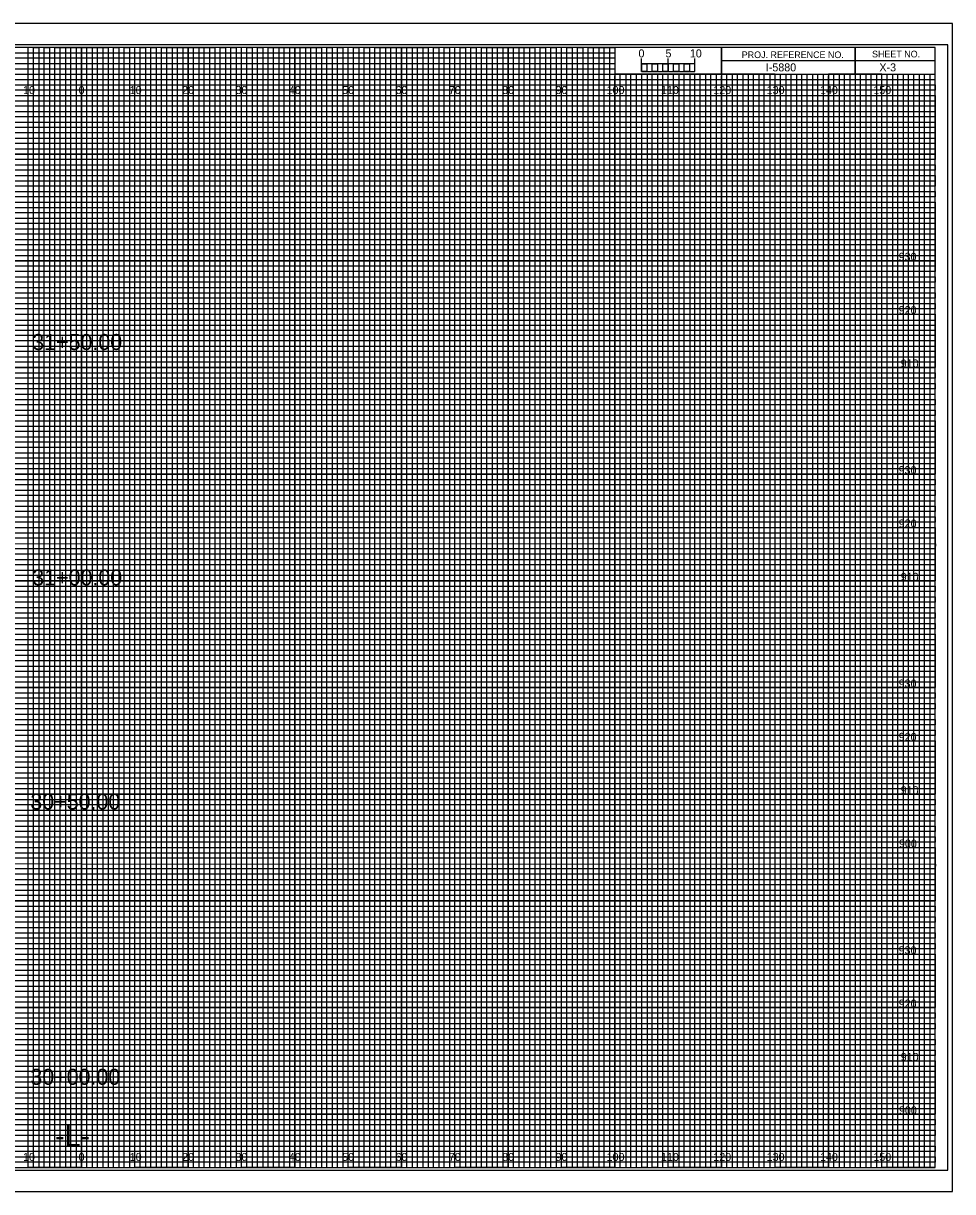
# Model space of a CAD drawing. Extents: x -13 to 323, y -4 to 3074.
# Drawn here: x 149.1 to 323.3, y 215.5 to 434.5 of the extents above; entities that cross this region are included whole.
import ezdxf

# ---------------------------------------------------------------- set-up
doc = ezdxf.new("R2010")
doc.units = 0
for name, color, linetype in [('Prop XS Alignment Label', 7, 'Continuous'), ('Prop XS Bar Scale Labels', 7, 'Continuous'), ('Prop XS Elevation Labels', 7, 'Continuous'), ('Prop XS Offset Labels', 7, 'Continuous'), ('Prop XS Project Number', 7, 'Continuous'), ('Prop XS Sheet Number', 7, 'Continuous'), ('Prop XS Station Labels', 7, 'Continuous'), ('Sheet Cross Section CELL', 7, 'Continuous'), ('Sheet Cross Section Grid Major CELL', 7, 'Continuous'), ('Sheet Cross Section Grid Middle CELL', 7, 'Continuous'), ('Sheet Cross Section Grid Minor 1 CELL', 7, 'Continuous'), ('Sheet Cross Section Grid Minor 2 CELL', 7, 'Continuous'), ('Sheet Cross Section Scale CELL', 7, 'Continuous'), ('Sheet Cutting Line CELL', 7, 'Continuous'), ('Sheet DOT Grid CELL', 7, 'Continuous'), ('Sheet Plot Border Inside CELL', 7, 'Continuous'), ('Sheet Plot Border Outside CELL', 7, 'Continuous')]:
    doc.layers.add(name, color=color, linetype=linetype)

msp = doc.modelspace()

# ---------------------------------------------------------------- linework, layer by layer
at = {"layer": 'Sheet Cross Section CELL'}
for p, q in [((305, 430), (305, 425)), ((305, 425), (305, 430)), ((280, 427.5), (280, 425)), ((320, 427.49), (280, 427.49)), ((280, 425), (320, 425))]:
    msp.add_line(p, q, dxfattribs=at)
for points in [[(320, 430), (0, 430), (0, 220), (320, 220)], [(280, 430), (260, 430), (260, 425.03), (280, 425.03)], [(320, 430), (280, 430), (280, 425), (320, 425)]]:
    msp.add_lwpolyline(points, close=True, dxfattribs=at)
at = {"layer": 'Sheet Cross Section Grid Major CELL'}
for p, q in [((150, 430), (140, 430)), ((150, 220), (150, 430)), ((170, 430), (160, 430)), ((160, 430), (160, 220)), ((170, 220), (170, 430)), ((190, 430), (180, 430)), ((180, 430), (180, 220)), ((190, 220), (190, 430)), ((210, 430), (200, 430)), ((200, 430), (200, 220)), ((210, 220), (210, 430)), ((230, 430), (220, 430)), ((220, 430), (220, 220)), ((230, 220), (230, 430)), ((250, 430), (240, 430)), ((240, 430), (240, 220)), ((250, 220), (250, 430)), ((260, 430), (260, 220)), ((270, 220), (270, 425)), ((290, 425), (280, 425)), ((280, 425), (280, 220)), ((290, 220), (290, 425)), ((310, 425), (300, 425)), ((300, 425), (300, 220)), ((310, 220), (310, 425)), ((160, 220), (150, 220)), ((180, 220), (170, 220)), ((200, 220), (190, 220)), ((220, 220), (210, 220)), ((240, 220), (230, 220)), ((260, 220), (250, 220)), ((280, 220), (270, 220)), ((300, 220), (290, 220)), ((320, 220), (310, 220)), ((320, 220), (320, 220))]:
    msp.add_line(p, q, dxfattribs=at)
for points in [[(0, 420), (320, 420), (320, 410), (0, 410)], [(0, 400), (320, 400), (320, 390), (0, 390)], [(0, 380), (320, 380), (320, 370), (0, 370)], [(0, 360), (320, 360), (320, 350), (0, 350)], [(0, 340), (320, 340), (320, 330), (0, 330)], [(0, 320), (320, 320), (320, 310), (0, 310)], [(0, 300), (320, 300), (320, 290), (0, 290)], [(0, 280), (320, 280), (320, 270), (0, 270)], [(0, 260), (320, 260), (320, 250), (0, 250)], [(0, 240), (320, 240), (320, 230), (0, 230)]]:
    msp.add_lwpolyline(points, dxfattribs=at)
at = {"layer": 'Sheet Cross Section Grid Middle CELL'}
for points in [[(145, 220), (155, 220), (155, 430), (165, 430), (165, 220), (175, 220), (175, 430), (185, 430), (185, 220), (195, 220), (195, 430), (205, 430), (205, 220), (215, 220), (215, 430), (225, 430), (225, 220), (235, 220), (235, 430), (245, 430), (245, 220), (255, 220), (255, 430), (259.93, 430), (260, 430), (260, 425), (264.99, 425), (264.99, 220), (275, 220), (275, 425), (285, 425), (285, 220), (295, 220), (295, 425), (305, 425), (305, 220), (315, 220), (315, 425)], [(0, 425), (275, 425)], [(0, 405), (320, 405), (320, 415), (0, 415)], [(0, 385), (320, 385), (320, 395), (0, 395)], [(0, 365), (320, 365), (320, 375), (0, 375)], [(0, 345), (320, 345), (320, 355), (0, 355)], [(0, 325), (320, 325), (320, 335), (0, 335)], [(0, 305), (320, 305), (320, 315), (0, 315)], [(0, 285), (320, 285), (320, 295), (0, 295)], [(0, 265), (320, 265), (320, 275), (0, 275)], [(0, 245), (320, 245), (320, 255), (0, 255)], [(0, 225), (320, 225), (320, 235), (0, 235)]]:
    msp.add_lwpolyline(points, dxfattribs=at)
at = {"layer": 'Sheet Cross Section Grid Minor 1 CELL'}
for p, q in [((0, 429), (260, 429)), ((260, 427.98), (0, 427.98)), ((260, 429), (260, 427.98)), ((0, 427), (260, 427)), ((260, 425.89), (0, 425.89)), ((260, 427), (260, 425.89)), ((0, 424), (320, 424))]:
    msp.add_line(p, q, dxfattribs=at)
for points in [[(0, 423), (270, 423), (320, 423), (320, 422), (0, 422)], [(0, 421), (320, 421), (320, 419), (0, 419)], [(0, 418), (320, 418), (320, 417), (0, 416.98)], [(0, 416), (320, 416), (320, 414), (0, 414)], [(0, 413), (320, 413), (320, 412), (0, 412)], [(0, 411), (320, 411), (320, 409), (0, 409)], [(0, 408), (320, 408), (320, 407), (0, 407)], [(0, 406), (320, 406), (320, 404), (0, 404)], [(0, 403), (320, 403), (320, 402), (0, 402)], [(0, 401), (320, 401), (320, 399), (0, 399)], [(0, 398), (320, 398), (320, 397), (0, 397)], [(0, 396), (320, 396), (320, 393.95), (320, 393), (320, 392), (0, 392)], [(0, 394), (320, 394), (320, 393), (0, 393)], [(0, 391), (320, 391), (320, 389), (0, 389.03)], [(0, 389.03), (320, 389), (320, 388), (0, 388)], [(0, 387), (320, 387), (320, 386), (0, 386)], [(0, 384), (320, 384), (320, 383), (0, 383)], [(0, 382), (320, 382), (320, 381), (0, 381)], [(-0.07, 378.89), (320, 378.89), (320, 377.88), (-0.07, 377.88)], [(0, 377), (320, 377), (320, 376), (0, 376)], [(0, 374), (320, 374), (320, 373), (0, 373)], [(0, 372), (320, 372), (320, 371), (0, 371)], [(0, 369), (320, 369), (320, 368), (0, 368)], [(0, 367), (320, 367), (320, 366), (0, 366)], [(0, 364), (320, 364), (320, 363), (0, 363)], [(0, 362), (320, 362), (320, 361), (0, 361)], [(0, 359), (320, 359), (319.99, 357.98), (0, 358)], [(0, 357), (320, 357), (320, 356), (0, 356)], [(0, 354), (320, 354), (320, 353), (0, 353)], [(0, 352), (320, 352), (320, 351), (0, 351)], [(0, 349), (320, 349), (320, 348), (0, 348)], [(0, 347), (320, 347), (320, 346), (0, 346)], [(0, 344), (320, 344), (320, 343), (0, 343)], [(0, 342), (320, 342), (320, 341), (0, 341)], [(0, 339), (320, 339), (320, 338), (0, 338)], [(0, 336.99), (320.07, 336.91), (320, 336), (0, 336)], [(0, 334), (320, 334), (320, 333), (0, 333)], [(0, 332), (320, 332), (320, 331), (0, 331)], [(0, 329), (320, 329), (320, 328), (0, 328)], [(0, 327), (320, 327), (320, 326), (0, 326)], [(0, 324), (320, 324), (320, 323), (0, 323)], [(0, 322), (320, 322), (320, 321), (0, 321)], [(0, 319), (320, 319), (320, 318), (0, 318)], [(0, 317), (320, 317), (320, 316), (0, 316)], [(0, 314), (320, 314), (320, 313), (0, 313)], [(0, 312), (320, 312), (320, 311), (0, 311)], [(0, 309), (320, 309), (320, 308), (0, 308)], [(0, 307), (320, 307), (320, 306), (0, 306)], [(0, 304), (320, 304), (320, 303), (0, 303)], [(0, 302), (320, 302), (320, 301), (0, 301)], [(0, 299), (320, 299), (319.99, 297.98), (0, 298)], [(0, 297), (320, 297), (320, 296), (0, 296)], [(0, 294), (320, 294), (320, 293), (0, 293)], [(0, 292), (320, 292), (320, 291), (0, 291)], [(0, 289), (320, 289), (320, 288), (0, 288)], [(0, 287), (320, 287), (320, 286), (0, 286)], [(0, 284), (320, 284), (320, 283), (0, 283)], [(0, 282), (320, 282), (320, 281), (0, 281)], [(0, 279), (320, 279), (320, 278), (0, 278)], [(0, 276.99), (320.07, 276.91), (320, 276), (0, 276)], [(0, 274), (320, 274), (320, 273), (0, 273)], [(0, 272), (320, 272), (320, 271), (0, 271)], [(0, 269), (320, 269), (320, 268), (0, 268)], [(0, 267), (320, 267), (320, 266), (0, 266)], [(0, 264), (320, 264), (320, 263), (0, 263)], [(0, 262), (320, 262), (320, 261), (0, 261)], [(0, 259), (320, 259), (320, 258), (0, 258)], [(0, 257), (320, 257), (320, 256), (0, 256)], [(0, 254), (320, 254), (320, 253), (0, 253)], [(0, 252), (320, 252), (320, 251), (0, 251)], [(0, 249), (320, 249), (320, 248), (0, 248)], [(0, 247), (320, 247), (320, 246), (0, 246)], [(0, 244), (320, 244), (320, 243), (0, 243)], [(0, 242), (320, 242), (320, 241), (0, 241)], [(0, 239), (320, 239), (320, 238), (0, 238)], [(0, 237), (320, 237), (320, 236), (0, 236)], [(0, 234), (320, 234), (320, 233), (0, 233)], [(0, 232), (320, 232), (320, 231), (0, 231)], [(0, 229), (320, 229), (320, 228), (0, 228)], [(0, 227), (320, 227), (320, 226), (0, 226)], [(0, 224), (320, 224), (320, 223), (0, 223)], [(0, 222), (320, 222), (320, 221), (0, 221)]]:
    msp.add_lwpolyline(points, dxfattribs=at)
at = {"layer": 'Sheet Cross Section Grid Minor 2 CELL'}
for p, q in [((267, 425), (266.01, 425)), ((266.01, 425), (266.01, 220)), ((267, 220), (267, 425)), ((269, 425), (268, 425)), ((268, 425), (268, 220)), ((269, 220), (269, 425)), ((266.01, 220), (265, 220)), ((268, 220), (267, 220))]:
    msp.add_line(p, q, dxfattribs=at)
for points in [[(150, 220), (151, 220), (151, 430), (152, 430), (152, 220)], [(152, 220), (153, 220), (153, 430), (154, 430), (154, 220)], [(155, 220), (156, 220), (156, 430), (157, 430), (157, 220)], [(157, 220), (158, 220), (158, 430), (159, 430), (159, 220)], [(160, 220), (161, 220), (161, 430), (162, 430), (162, 220)], [(162, 220), (163, 220), (163, 430), (164, 430), (164, 220)], [(165, 220), (166, 220), (166, 430), (167, 430), (167, 220)], [(167, 220), (168, 220), (168, 430), (169, 430), (169, 220)], [(170, 220), (171, 220), (171, 430), (172, 430), (172, 220)], [(172, 220), (173, 220), (173, 430), (174, 430), (174, 220)], [(175, 220), (176, 220), (176, 430), (177, 430), (177, 220)], [(177, 220), (178, 220), (178, 430), (179, 430), (179, 220)], [(180, 220), (181, 220), (181, 430), (182, 430), (182, 220)], [(182, 220), (183, 220), (183, 430), (184, 430), (184, 220)], [(185, 220), (186, 220), (186, 430), (187, 430), (187, 220)], [(187, 220), (188, 220), (188, 430), (189, 430), (189, 220)], [(190, 220), (191, 220), (191, 430), (192, 430), (192, 220)], [(192, 220), (193, 220), (193, 430), (194, 430), (194, 220)], [(195, 220), (196, 220), (196, 430), (197, 430), (197, 220)], [(197, 220), (198, 220), (198, 430), (199, 430), (199, 220)], [(200, 220), (201, 220), (201, 430), (202, 430), (202, 220)], [(202, 220), (203, 220), (203, 430), (204, 430), (204, 220)], [(205, 220), (206, 220), (206, 430), (207, 430), (207, 220)], [(207, 220), (208, 220), (208, 430), (209, 430), (209, 220)], [(210, 220), (211, 220), (211, 430), (212, 430), (212, 220)], [(212, 220), (213, 220), (213, 430), (214, 430), (214, 220)], [(215, 220), (216, 220), (216, 430), (217, 430), (217, 220)], [(217, 220), (218, 220), (218, 430), (219, 430), (219, 220)], [(220, 220), (221, 220), (221, 430), (222, 430), (222, 220)], [(222, 220), (223, 220), (223, 430), (224, 430), (224, 220)], [(225, 220), (226, 220), (226, 430), (227, 430), (227, 220)], [(227, 220), (228, 220), (228, 430), (229, 430), (229, 220)], [(230, 220), (231, 220), (231, 430), (232, 430), (232, 220)], [(232, 220), (233, 220), (233, 430), (234, 430), (234, 220)], [(235, 220), (236, 220), (236, 430), (237, 430), (237, 220)], [(237, 220), (238, 220), (238, 430), (239, 430), (239, 220)], [(240, 220), (241, 220), (241, 430), (242, 430), (242, 220)], [(242, 220), (243, 220), (243, 430), (244, 430), (244, 220)], [(245, 220), (246, 220), (246, 430), (247, 430), (247, 220)], [(247, 220), (248, 220), (248, 430), (249, 430), (249, 220)], [(250, 220), (251, 220), (251, 430), (252, 430), (252, 220)], [(252, 220), (253, 220), (253, 430), (254, 430), (254, 220)], [(255, 220), (256, 220), (256, 430), (257, 430), (257, 220)], [(257, 220), (258, 220), (258, 430), (259, 430), (259, 220)], [(260, 220), (261, 220), (261, 425), (262.02, 425), (262.02, 220)], [(262, 220), (263, 220), (263, 425), (263.99, 425), (263.99, 220)], [(270, 220), (270.98, 220), (270.98, 425), (272, 425), (272, 220)], [(272, 220), (273, 220), (273, 425), (274.05, 425), (274.05, 220)], [(275, 220), (276, 220), (276, 425), (277, 425), (277, 220)], [(277, 220), (278, 220), (278, 425), (279, 425), (279, 220)], [(280, 220), (281, 220), (281, 425), (282, 425), (282, 220)], [(282, 220), (283, 220), (283, 425), (284, 425), (284, 220)], [(285, 220), (286, 220), (286, 425), (287, 425), (287, 220)], [(287, 220), (288, 220), (288, 425), (289, 425), (289, 220)], [(290, 220), (291, 220), (291, 425), (292, 425), (292, 220)], [(292, 220), (293, 220), (293, 425), (294, 425), (294, 220)], [(295, 220), (296, 220), (296, 425), (297, 425), (297, 220)], [(297, 220), (298, 220), (298, 425), (299, 425), (299, 220)], [(300, 220), (301, 220), (301, 425), (302, 425), (302, 220)], [(302, 220), (303, 220), (303, 425), (304, 425), (304, 220)], [(305, 220), (306, 220), (306, 425), (307, 425), (307, 220)], [(307, 220), (308, 220), (308, 425), (309, 425), (309, 220)], [(310, 220), (311, 220), (311, 425), (312, 425), (312, 220)], [(312, 220), (313, 220), (313, 425), (314, 425), (314, 220)], [(315, 220), (316, 220), (316, 425), (317, 425), (317, 220)], [(317, 220), (318, 220), (318, 425), (319, 425), (319, 220)]]:
    msp.add_lwpolyline(points, dxfattribs=at)
at = {"layer": 'Sheet Cross Section Scale CELL'}
for p, q in [((265, 425.49), (265, 427.9)), ((265, 426.9), (265, 427.9)), ((270, 425.49), (270, 427.9)), ((275, 425.49), (275, 427.9)), ((275, 426.9), (275, 427.9))]:
    msp.add_line(p, q, dxfattribs=at)
for points in [[(275, 426.9), (265, 426.9), (265, 425.49), (275, 425.49)], [(265, 426.9), (266, 426.9), (266, 425.49), (265, 425.49)], [(267, 426.9), (268, 426.9), (268, 425.49), (267, 425.49)], [(269, 426.9), (270, 426.9), (270, 425.49), (269, 425.49)], [(271, 426.9), (272, 426.9), (272, 425.49), (271, 425.49)], [(273, 426.9), (274, 426.9), (274, 425.49), (273, 425.49)]]:
    msp.add_lwpolyline(points, close=True, dxfattribs=at)
at = {"layer": 'Sheet Cutting Line CELL'}
for p, q in [((323.3, 434.5), (-13.4, 434.5)), ((-13.4, 215.5), (323.3, 215.5))]:
    msp.add_line(p, q, dxfattribs=at)
at = {"layer": 'Sheet DOT Grid CELL'}
for p, q in [((150, 220), (150, 430)), ((160, 220), (160, 430)), ((170, 220), (170, 430)), ((180, 220), (180, 430)), ((190, 220), (190, 430)), ((200, 220), (200, 430)), ((210, 220), (210, 430)), ((220, 220), (220, 430)), ((230, 220), (230, 430)), ((240, 220), (240, 430)), ((250, 220), (250, 430)), ((260, 220), (260, 424.69)), ((270, 220), (270, 424.69)), ((280, 220), (280, 424.69)), ((290, 220), (290, 424.69)), ((300, 220), (300, 424.69)), ((310, 220), (310, 424.69)), ((0, 420), (320, 420)), ((0, 410), (320, 410)), ((0, 400), (320, 400)), ((0, 390), (320, 390)), ((0, 380), (320, 380)), ((0, 370), (320, 370)), ((0, 360), (320, 360)), ((0, 350), (320, 350)), ((0, 340), (320, 340)), ((0, 330), (320, 330)), ((0, 320), (320, 320)), ((0, 310), (320, 310)), ((0, 300), (320, 300)), ((0, 290), (320, 290)), ((0, 280), (320, 280)), ((0, 270), (320, 270)), ((0, 260), (320, 260)), ((0, 250), (320, 250)), ((0, 240), (320, 240)), ((0, 230), (320, 230))]:
    msp.add_line(p, q, dxfattribs=at)
at = {"layer": 'Sheet Plot Border Inside CELL'}
msp.add_lwpolyline([(-10.8, 219.5), (322.4, 219.5), (322.4, 430.5), (-10.8, 430.5)], close=True, dxfattribs=at)
at = {"layer": 'Sheet Plot Border Outside CELL'}
msp.add_lwpolyline([(-13.4, 215.5), (323.3, 215.5), (323.3, 434.5), (-13.4, 434.5)], close=True, dxfattribs=at)

# ---------------------------------------------------------------- texts
at = {"layer": 'Prop XS Alignment Label'}
msp.add_text('-L-', height=4, dxfattribs=at).set_placement((155.06, 224))
at = {"layer": 'Prop XS Bar Scale Labels'}
for s, p in [('5', (269.47, 428.12)), ('10', (274.04, 428.12))]:
    msp.add_text(s, height=1.5, dxfattribs=at).set_placement(p)
at = {"layer": 'Prop XS Elevation Labels'}
for s, p in [('930', (313.18, 390)), ('920', (313.19, 380)), ('910', (313.57, 370)), ('930', (313.18, 350)), ('920', (313.19, 340)), ('910', (313.57, 330)), ('930', (313.18, 310)), ('920', (313.19, 300)), ('910', (313.57, 290)), ('900', (313.24, 280)), ('930', (313.18, 260)), ('920', (313.19, 250)), ('910', (313.57, 240)), ('900', (313.24, 230))]:
    msp.add_text(s, height=1.5, dxfattribs=at).set_placement(p)
at = {"layer": 'Prop XS Offset Labels'}
for s, p in [('10', (149.04, 421.25)), ('0', (159.45, 421.25)), ('0', (159.45, 421.25)), ('10', (169.04, 421.25)), ('20', (178.86, 421.25)), ('30', (188.86, 421.25)), ('40', (198.86, 421.25)), ('50', (208.86, 421.25)), ('60', (218.86, 421.25)), ('70', (228.86, 421.25)), ('80', (238.86, 421.25)), ('90', (248.86, 421.25)), ('100', (258.44, 421.25)), ('110', (268.62, 421.25)), ('120', (278.44, 421.25)), ('130', (288.44, 421.25)), ('140', (298.44, 421.25)), ('150', (308.44, 421.25)), ('10', (149.04, 221.25)), ('0', (159.45, 221.25)), ('0', (159.45, 221.25)), ('10', (169.04, 221.25)), ('20', (178.86, 221.25)), ('30', (188.86, 221.25)), ('40', (198.86, 221.25)), ('50', (208.86, 221.25)), ('60', (218.86, 221.25)), ('70', (228.86, 221.25)), ('80', (238.86, 221.25)), ('90', (248.86, 221.25)), ('100', (258.44, 221.25)), ('110', (268.62, 221.25)), ('120', (278.44, 221.25)), ('130', (288.44, 221.25)), ('140', (298.44, 221.25)), ('150', (308.44, 221.25))]:
    msp.add_text(s, height=1.5, dxfattribs=at).set_placement(p)
at = {"layer": 'Prop XS Project Number'}
msp.add_text('I-5880', height=1.5, dxfattribs=at).set_placement((288.28, 425.5))
at = {"layer": 'Prop XS Sheet Number'}
msp.add_text('X-3', height=1.5, dxfattribs=at).set_placement((309.57, 425.5))
at = {"layer": 'Prop XS Station Labels'}
for s, p in [('31+50.00', (150.77, 373.27)), ('31+00.00', (150.77, 329.14)), ('30+50.00', (150.41, 287.13)), ('30+00.00', (150.41, 235.53))]:
    msp.add_text(s, height=3, dxfattribs=at).set_placement(p)
at = {"layer": 'Sheet Cross Section CELL'}
for s, p in [('PROJ. REFERENCE NO.', (283.77, 427.99)), ('SHEET NO.', (308.19, 428.12))]:
    msp.add_text(s, height=1.25, dxfattribs=at).set_placement(p)
at = {"layer": 'Sheet Cross Section Scale CELL'}
msp.add_text('0', height=1.5, dxfattribs=at).set_placement((264.41, 428.12))

doc.saveas('drawing.dxf')
